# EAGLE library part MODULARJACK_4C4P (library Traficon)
Modular jack 4c/4p Farnell: 973-4171 Molex: 85502-0005 (in the future 85502-5005)
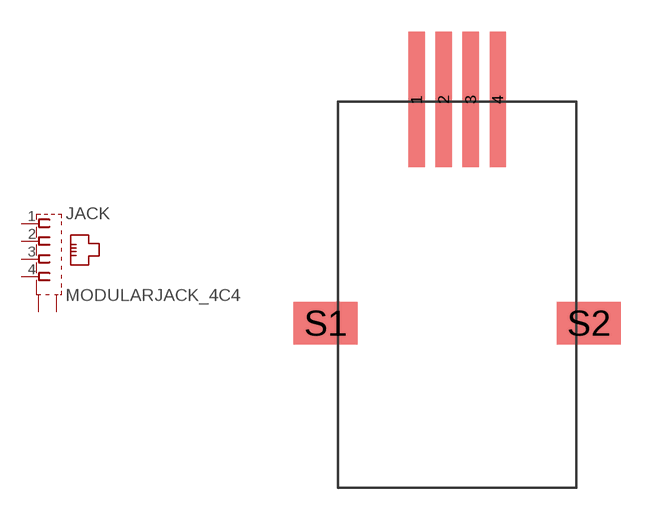
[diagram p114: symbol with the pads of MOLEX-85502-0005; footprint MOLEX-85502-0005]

Designator prefix JACK

## MODULARJACK_4C4P  [MOLEX-85502-0005]
1  1  pas
2  2  pas
3  3  pas
4  4  pas
S1  S1  pas
S2  S2  pas

## Footprint MOLEX-85502-0005 (pad centres in mm)
smd 0.762 x 6.35: 1 -1.905,8.255; 2 -0.635,8.255; 3 0.635,8.255; 4 1.905,8.255
smd 3 x 2: S1 -6.172,-2.235; S2 6.172,-2.235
